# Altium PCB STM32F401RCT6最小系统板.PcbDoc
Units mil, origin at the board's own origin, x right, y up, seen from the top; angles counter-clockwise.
Board outline 2560 x 2610 mil, 2 copper layers (Top Layer, Bottom Layer); 73 components, 77 nets, 277 pads, 58 vias.
Unrouted connection lines stored in the file: 63.
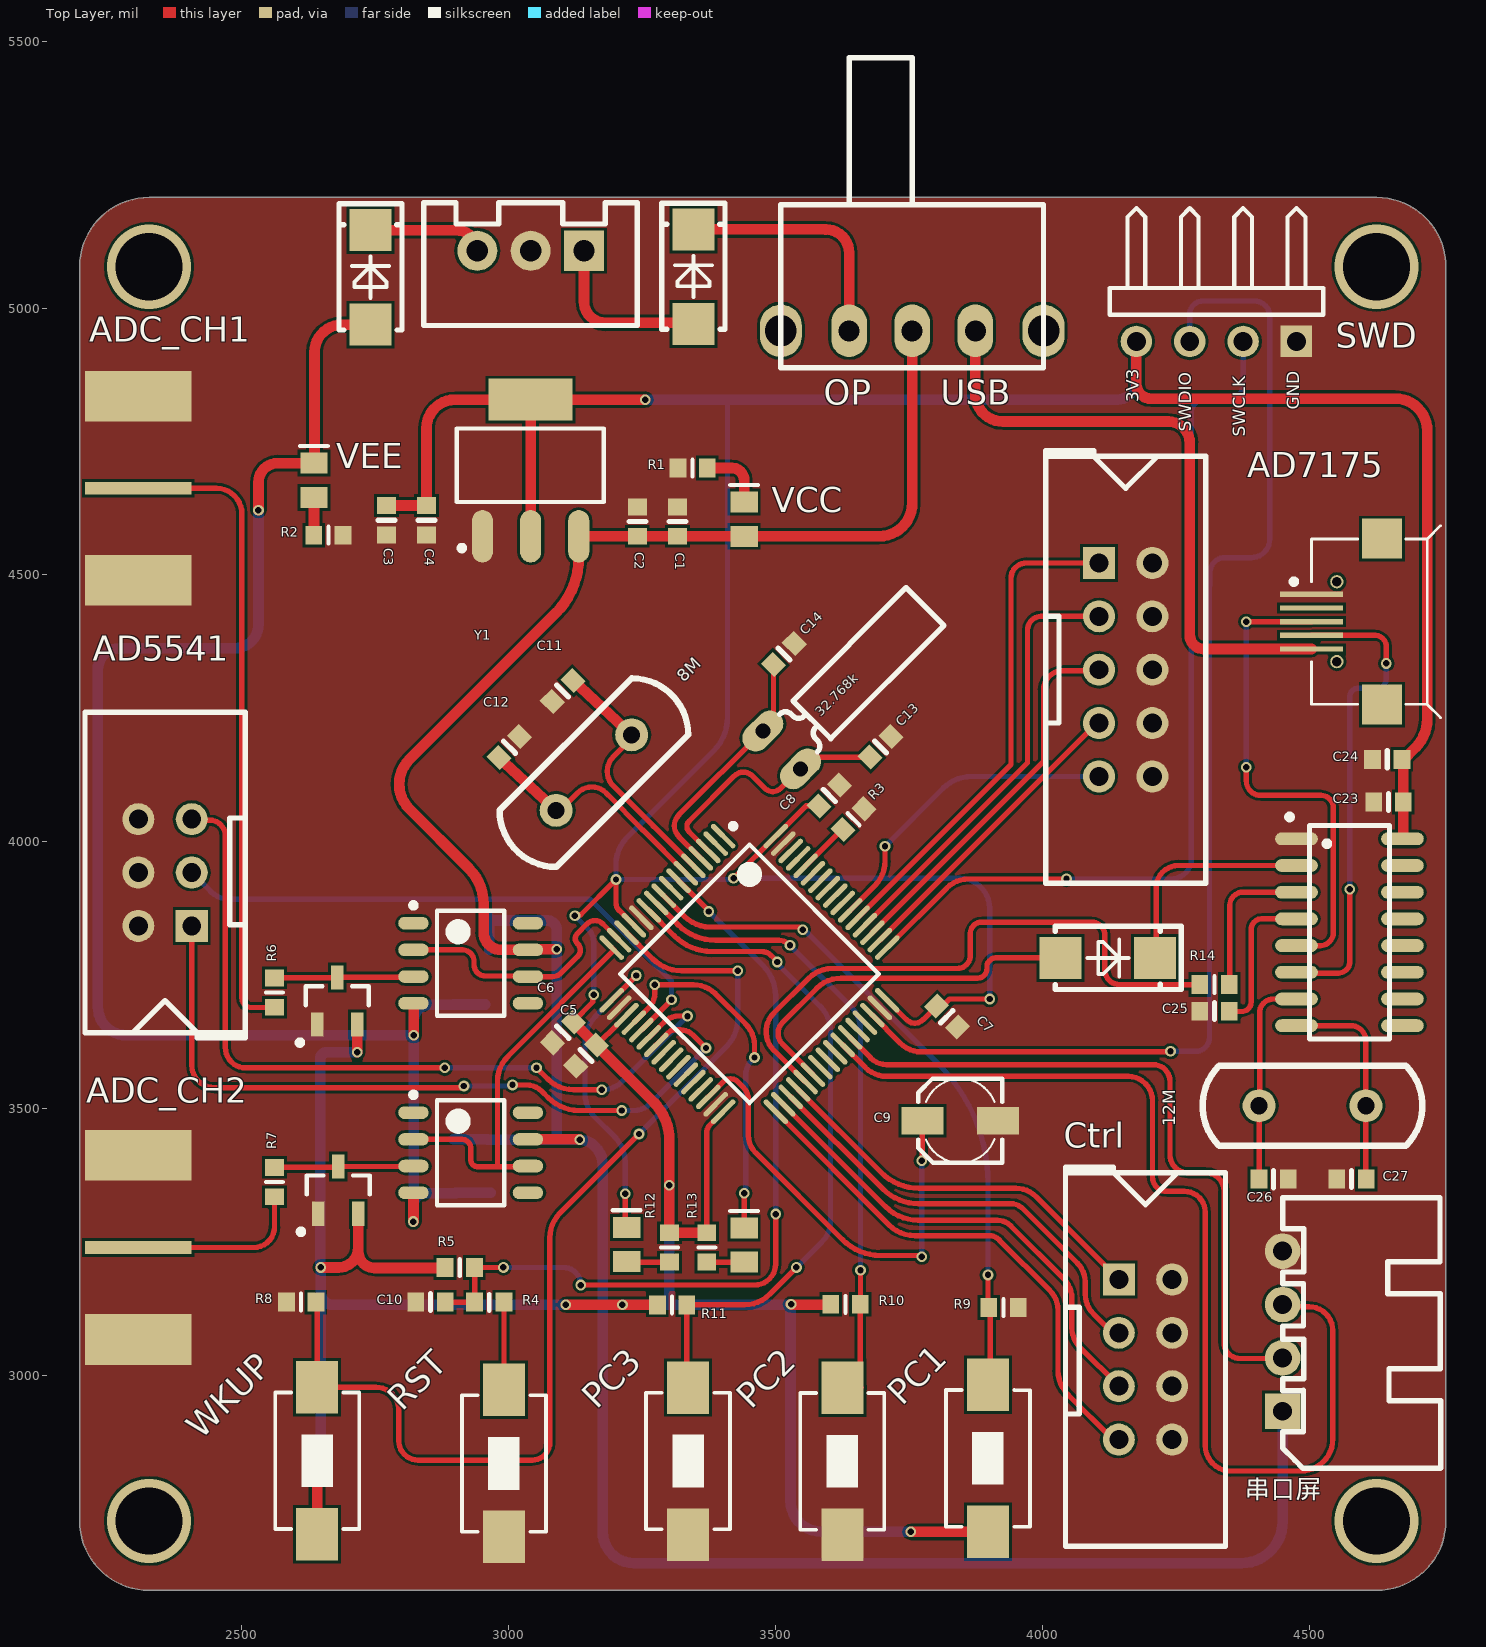
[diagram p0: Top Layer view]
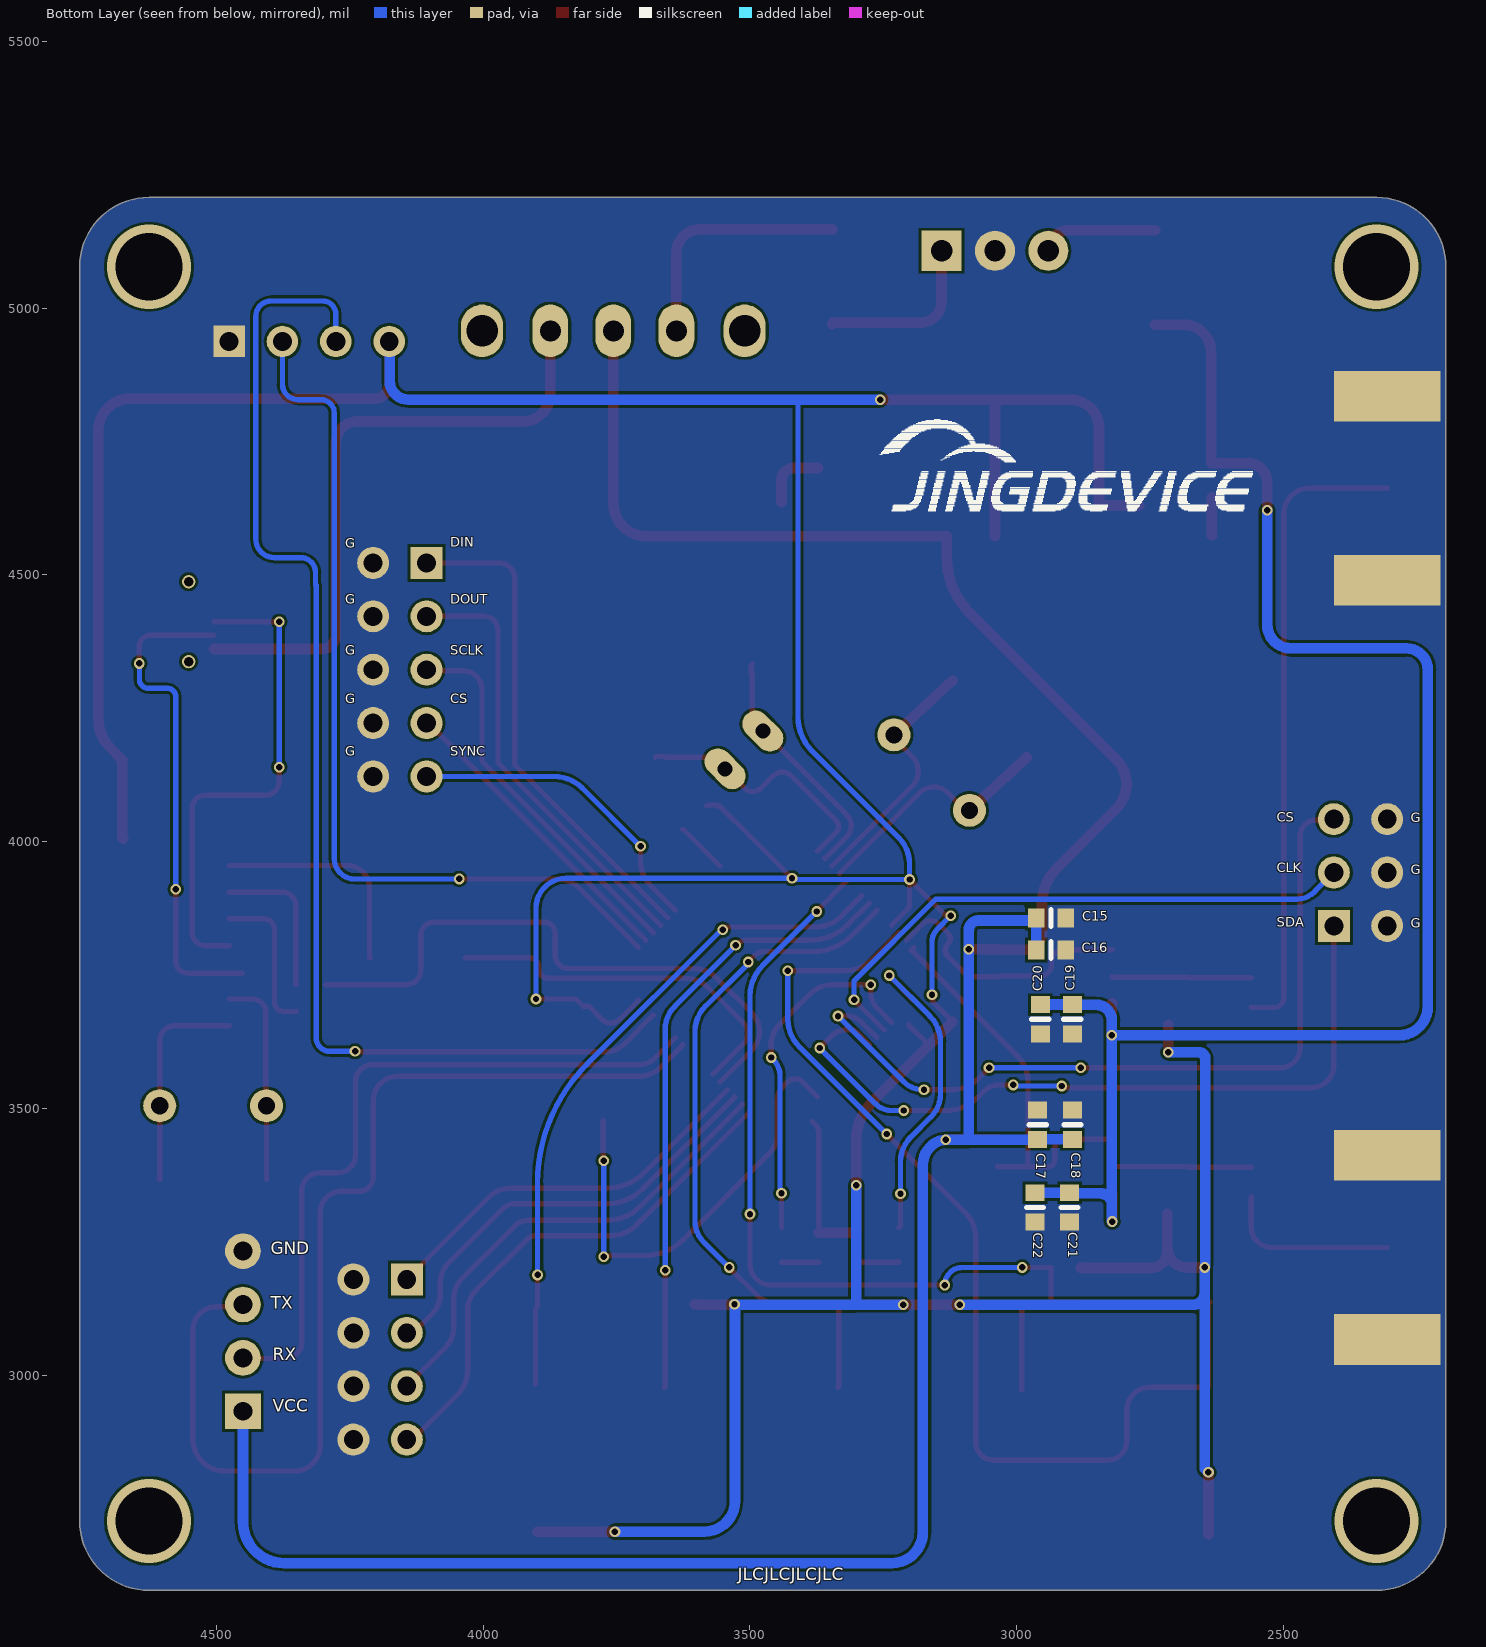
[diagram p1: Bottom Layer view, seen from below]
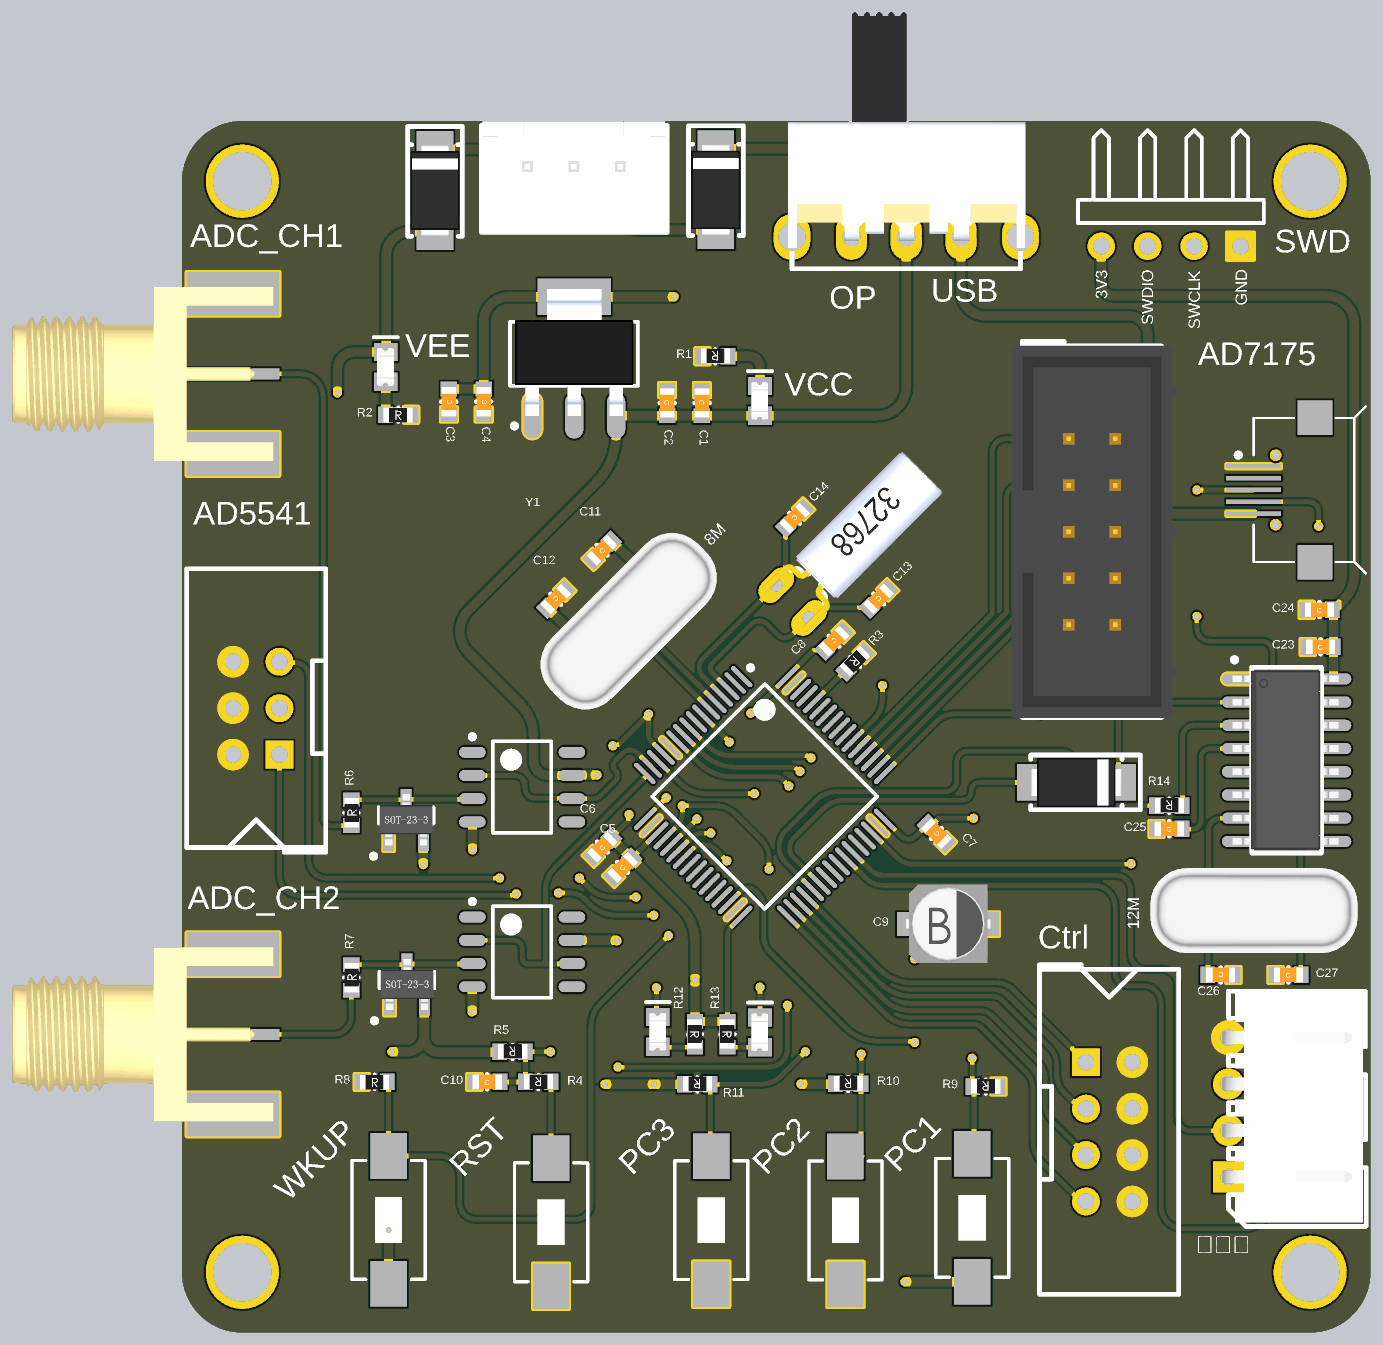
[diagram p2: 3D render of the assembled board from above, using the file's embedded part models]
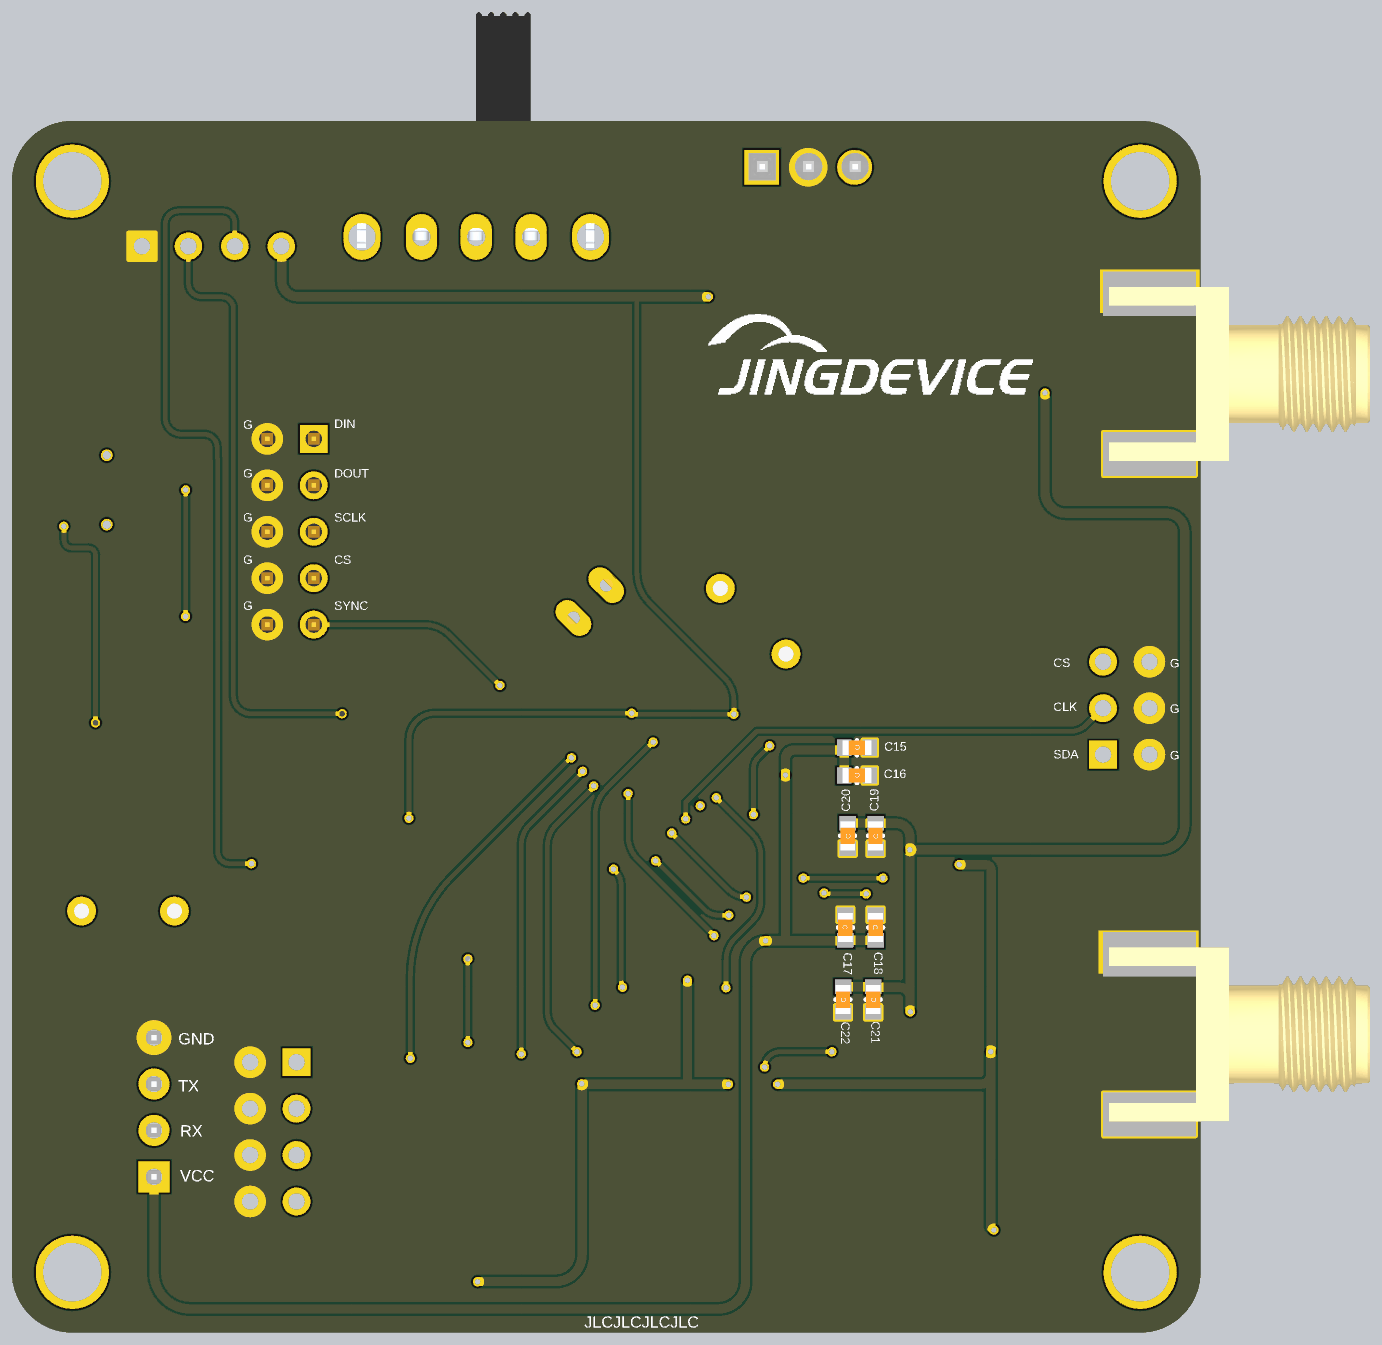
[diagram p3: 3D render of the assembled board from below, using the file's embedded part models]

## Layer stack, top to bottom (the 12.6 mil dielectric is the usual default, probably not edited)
Top Solder: solder mask 0.4, Solder Resist, Dk 3.5
Top Layer: signal copper 1.4
Dielectric 1: dielectric 12.6, FR-4, Dk 4.8
Bottom Layer: signal copper 1.4
Bottom Solder: solder mask 0.4, Solder Resist, Dk 3.5

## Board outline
2325.94,2597.49 cw(c2325.94,2727.49) 2195.94,2727.49 2195.94,5077.49 cw(c2325.94,5077.49) 2325.94,5207.49 4625.94,5207.49 cw(c4625.94,5077.49) 4755.94,5077.49 4755.94,2727.49 cw(c4625.94,2727.49) 4625.94,2597.49

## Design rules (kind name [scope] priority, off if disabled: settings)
Clearance [All] p1: gap=5 ignorepadtopadclearanceinfootprint=FALSE except(0: Arc-Hole Track-Hole SMDPad-Hole THPad-Hole Via-Hole Fill-Hole Poly-Hole Region-Hole Text-Hole)
PolygonConnect [All] p1: connectstyle=Direct reliefconductorwidth=10 reliefentries=4 polygonreliefangle="90 Angle" airgapwidth=10
RoutingVias [All] p1: holewidth=28 width=50 viastyle="Through Hole" minholewidth=28 minwidth=50 maxholewidth=28 maxwidth=50
SolderMaskExpansion [All] p1: expansion=4 istentingtop=FALSE
Width [All] p1: maxlimit=100 minlimit=10 preferedwidth=10
30 further rules are at their usual default settings.

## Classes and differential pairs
component class USB-TTL: C23 C24 C25 C26 C27 R14
component class STM32F401RCT6最小系统板: AD5541 AD7175 C1 C2 C3 C4 C5 C6 C7 C8 C9 C10 C11 C12 C13 C14 R1 R2 R3 R4 R5 RST SWD Y1 串口屏
component class Keys: R8 R9 R10 R11 R12 R13 WKUP
component class Analog: ADC_CH1 ADC_CH2 C15 C16 C17 C18 C19 C20 C21 C22 R6 R7

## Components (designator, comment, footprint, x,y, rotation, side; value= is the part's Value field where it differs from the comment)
AD5541 "DC-6P" DC-6P 2350.94,4027.49 r90 top
AD7175 "DC-10P" DC-10P 4105.94,4322.49 r90 top
ADC_CH1 "SMA" SMA1 2305.94,4662.49 r0 top
ADC_CH2 "SMA" SMA1 2305.94,3239.99 r0 top
C1 "Cap-S" C0603-L 3315.94,4600.05 r270 top value=100nF
C2 "Cap-S" C0603-L 3240.94,4600.05 r270 top value=10uF
C3 "Cap-S" C0603-L 2770.94,4602.49 r90 top value=100nF
C4 "Cap-S" C0603-L 2845.94,4602.49 r90 top value=10uF
C5 "Cap-S" C0603-L 3144.94,3599.49 r45 top value=100nF
C6 "Cap-S" C0603-L 3101.45,3643.01 r45 top value=10uF
C7 "Cap-S" C0603-L 3820.94,3672.49 r135 top value=100nF
C8 "Cap-S" C0603-L 3600.43,4086.98 r225 top value=10uF
C9 "C" C-RB-SD4 3845.94,3477.49 r0 top value=4.7uF
C10 "Cap-S" C0603-L 2853.38,3137.49 r0 top value=100nF
C11 "Cap-S" C0603-L 3100.94,4282.49 r45 top value=20pF
C12 "Cap-S" C0603-L 3000.94,4177.49 r225 top value=20pF
C13 "Cap-S" C0603-L 3696.45,4178.01 r225 top value=10pF
C14 "Cap-S" C0603-L 3515.43,4351.98 r225 top value=10pF
C15 "Cap-S" C0603-L 2935.94,3857.49 r0 bottom value=100nF
C16 "Cap-S" C0603-L 2935.94,3797.49 r0 bottom value=10uF
C17 "Cap-S" C0603-L 2960.94,3470.05 r270 bottom value=100nF
C18 "Cap-S" C0603-L 2895.94,3470.05 r270 bottom value=10uF
C19 "Cap-S" C0603-L 2895.94,3667.49 r90 bottom value=100nF
C20 "Cap-S" C0603-L 2955.94,3667.49 r90 bottom value=10uF
C21 "Cap-S" C0603-L 2900.94,3314.93 r90 bottom value=100nF
C22 "Cap-S" C0603-L 2965.94,3314.93 r90 bottom value=10uF
C23 "Cap-S" C0603-L 4648.38,4074.49 r0 top value=100nF
C24 "Cap-S" C0603-L 4645.94,4154.49 r0 top value=10uF
C25 "Cap-S" C0603-L 4322.38,3682.49 r0 top value=10nF
C26 "Cap-S" C0603-L 4433,3368 r180 top value=22pF
C27 "Cap-S" C0603-L 4579,3368 r0 top value=22pF
Ctrl "DC-8P" DC-8P 4201,3038 r270 top
D1 "D" D-SMA 2740.94,5057.49 r90 top
D2 "D" D-SMA 3345.94,5058.91 r90 top
D3 "D" D-SMA 4122.36,3782.49 r0 top
J1 "Power-3P" SIPA03 3140.94,5107.49 r180 top
LED3 "LED" Led-0805_L 3220.94,3245.49 r90 top
LED4 "LED" Led-0805_L 3440.94,3244.49 r90 top
PC1 "SW-PB2" SW-PB2-SMD 3898,2847 r180 top (schematic designator S1)
PC2 "SW-PB2" SW-PB2-SMD 3625,2837 r0 top (schematic designator S2)
PC3 "SW-PB2" SW-PB2-SMD 3335.94,2837.49 r0 top (schematic designator S3)
R1 "R" R0603-L 3344.38,4700.49 r180 top value=1K
R2 "R" R0603-L 2661.94,4574.49 r0 top value=1K
R3 "R" R0603-L 3645.94,4042.49 r225 top value=10K
R4 "R" R0603-L 2963.5,3137.49 r180 top value=100R
R5 "R" R0603-L 2907.94,3202.49 r180 top value=10K
R6 "R" R0603-L 2560.94,3717.49 r90 top value=100R
R7 "R" R0603-L 2560.94,3362.49 r90 top value=100R
R8 "R" R0603-L 2610.94,3137.49 r0 top value=1K
R9 "R" R0603-L 3926.94,3127.49 r180 top value=1K
R10 "R" R0603-L 3630.94,3133.49 r180 top value=1K
R11 "R" R0603-L 3305.94,3132.49 r180 top value=1K
R12 "R" R0603-L 3300.94,3240.05 r270 top value=1K
R13 "R" R0603-L 3370.94,3240.05 r270 top value=1K
R14 "R" R0603-L 4322.38,3732.49 r180 top value=100
RST "SW-PB2" SW-PB2-SMD 2990.94,2837.49 r180 top
SWD "Header 4H" HDR1X4H 4475.94,4937.49 r180 top
U1 "STM32F401RCT6" STM-LQFP64_L 3450.94,3752.49 r315 top
U3 "OPA192" SOIC127P600X175-8N 2928.66,3772.49 r0 top
U4 "OPA192" SOIC127P600X175-8N 2928.66,3417.49 r0 top
U5 "BAT54S" SOT-23-3 2678.95,3702 r90 top
U6 "BAT54S" SOT-23-3 2680.94,3347.49 r90 top
U7 "CH340G" SOP-16 4575.94,3839.49 r0 top
U10 "AMS1117" SOT-223 3040.94,4697.49 r0 top
USB "USB_Mini/Micro" USB_Micro 4720.94,4412.49 r0 top
USB "SW-SPDT" SW-SPDT 3755.94,4957.49 r90 top (schematic designator POWER)
VCC "LED" Led-0805_L 3440.94,4604.49 r90 top (schematic designator LED1)
VEE "LED" Led-0805_L 2634.94,4677.49 r90 top (schematic designator LED2)
WKUP "SW-PB2" SW-PB2-SMD 2640.94,2842.49 r180 top
Y1 "XTAL" XTAL-PB2-DIP 3160.94,4142.49 r45 top value=8M
Y2 "XTAL" XTAL-32768 3475.94,4207.49 r315 top value=32.768K
Y3 "XTAL" XTAL-PB2-DIP 4515.94,3513.49 r0 top value=12M
串口屏 "Header 4" XH2.54-WI-4P 4450,3083 r90 top

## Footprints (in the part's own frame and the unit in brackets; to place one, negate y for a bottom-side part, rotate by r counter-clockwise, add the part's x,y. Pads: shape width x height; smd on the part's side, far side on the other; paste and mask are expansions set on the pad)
C0603-L [mm] "贴片电容0603 高密度"
  rect 0.8x0.9 smd: 1(-0.7,0) 2(0.7,0)
  silkscreen extent 0,-0.39 0,0.41, body extent -0.8,-0.4 0.8,0.41, height 0.88
C-RB-SD4 [mm] "贴片铝电解"
  rect 2x1.3 smd: 1(-1.8,0) 2(1.8,0)
  silkscreen extent -2,-2 2,2, body extent -2.29,-2.14 2.31,2.16, height 5.2
D-SMA [mm]
  rect 2x2 smd: 1(-2.25,0) 2(2.25,0)
  silkscreen extent -2.5,-1.5 3.5,1.5, body extent -2.5,-1.35 2.5,1.35, height 2.15
DC-6P [mil]
  rect 60x60 hole 35.43: 1(-185,-55)
  round 60 hole 35.43: 2(-85,-55) 3(15,-55) 4(15,45) 5(-85,45) 6(-185,45)
  silkscreen extent -395,-155 215,145, body extent -386,-156 216,145, height 236
DC-8P [mil]
  rect 60x60 hole 35.43: 1(-142,-58)
  round 60 hole 35.43: 2(-42,-58) 3(58,-58) 4(158,-58) 5(158,42) 6(58,42) 7(-42,42) 8(-142,42)
  silkscreen extent -352,-158 358,142, body extent -342,-159 358,142, height 236
DC-10P [mil]
  rect 60x60 hole 35.43: 1(200,0)
  round 60 hole 35.43: 2(100,0) 3(0,0) 4(-100,0) 5(-200,0) 6(-200,-100) 7(-100,-100) 8(0,-100) 9(100,-100) 10(200,-100)
  silkscreen extent -400,-200 410,100, body extent -401,-233 401,123, height 357
HDR1X4H [mm] "Connector; Header; 4 Position; Right Angle"
  rect 1.5x1.5 hole 0.9: 1(0,0)
  round 1.5 hole 0.9: 2(2.54,0) 3(5.08,0) 4(7.62,0)
  silkscreen extent -1.27,-6.35 8.89,-1.27
Led-0805_L [mm] "贴片LED0805-高密度"
  rect 1x1.3 smd: 1(-0.813,0) 2(0.813,0)
  silkscreen extent 1.63,-0.66 1.63,0.66, body extent -1.03,-0.44 1.03,0.47, height 0.85
R0603-L [mm] "贴片电阻0603 高密度"
  rect 0.8x0.9 smd: 1(-0.7,0) 2(0.7,0)
  silkscreen extent 0,-0.39 0,0.41, body extent -0.81,-0.43 0.79,0.39, height 0.53
SIPA03 [mil]
  rect 75x75 hole 40: 1(0,0)
  round 75 hole 40: 2(100,0) 3(200,0)
  silkscreen extent -100,-90 300,140, body extent -96,-99 298,137, height 276
SMA1 [mil]
  rect 200x24 smd: 1(0,0)
  rect 200x95 smd: 2(0,-172.5) 2(0,172.5)
  rect 200x95 smd far side: 2(0,-172.5)
  rect 200x95 smd far side mask+4: 2(0,172.5)
  body extent -475,-187 87,187, height 171
SOIC127P600X175-8N [mm] "SOIC, 8-Leads, Body 4.91x3.90mm, Pitch 1.27mm, IPC Medium Density"
  oval 1.45x0.6 smd: 1(-2.725,1.905) 2(-2.725,0.635) 3(-2.725,-0.635) 4(-2.725,-1.905) 5(2.725,-1.905) 6(2.725,-0.635) 7(2.725,0.635) 8(2.725,1.905)
  silkscreen extent -2.85,-2.5 1.6,2.88, body extent -2,-2.5 2,2.5, height 1.75
SOP-16 [mil]
  oval 80x24 smd: 1(-100,166.09) 2(-100,116.09) 3(-100,66.09) 4(-100,16.09) 5(-100,-33.91) 6(-100,-83.91) 7(-100,-133.91) 8(-100,-183.91) 9(98.5,-183.91) 10(98.5,-133.91) 11(98.5,-83.91) 12(98.5,-33.91) 13(98.5,16.09) 14(98.5,66.09) 15(98.5,116.09) 16(98.5,166.09)
  silkscreen extent -118,-209 74,212, body extent -117,-202 111,184, height 69
SOT-23-3 [mm]
  rect 1.15x0.6 smd: 1(-1.13,0.96) 2(1.12,0.01) 3(-1.13,-0.94)
  silkscreen extent -2.11,-1.49 0.69,1.91, body extent -1.4,-1.45 1.4,1.45, height 1.2
SOT-223 [mm]
  oval 1x2.5 smd: 1(-2.29,-3.175) 2(0,-3.175) 3(2.29,-3.175)
  rect 4x2 smd: 2(0,3.325)
  silkscreen extent -3.52,-3.86 3.48,1.96, body extent -3.25,-3.2 3.25,3.76, height 1.66
STM-LQFP64_L [mm] "Thin QFP, 64-Leads, Body 10x10mm, Pitch 0.5mm, IPC High Density"
  oval 1.55x0.25 smd: 1(-5.525,3.75) 2(-5.525,3.25) 3(-5.525,2.75) 4(-5.525,2.25) 5(-5.525,1.75) 6(-5.525,1.25) 7(-5.525,0.75) 8(-5.525,0.25) 9(-5.525,-0.25) 10(-5.525,-0.75) 11(-5.525,-1.25) 12(-5.525,-1.75) 13(-5.525,-2.25) 14(-5.525,-2.75) 15(-5.525,-3.25) 16(-5.525,-3.75) 33(5.525,-3.75) 34(5.525,-3.25) 35(5.525,-2.75) 36(5.525,-2.25) 37(5.525,-1.75) 38(5.525,-1.25) 39(5.525,-0.75) 40(5.525,-0.25) 41(5.525,0.25) 42(5.525,0.75) 43(5.525,1.25) 44(5.525,1.75) 45(5.525,2.25) 46(5.525,2.75) 47(5.525,3.25) 48(5.525,3.75)
  oval 0.25x1.55 smd: 17(-3.75,-5.525) 18(-3.25,-5.525) 19(-2.75,-5.525) 20(-2.25,-5.525) 21(-1.75,-5.525) 22(-1.25,-5.525) 23(-0.75,-5.525) 24(-0.25,-5.525) 25(0.25,-5.525) 26(0.75,-5.525) 27(1.25,-5.525) 28(1.75,-5.525) 29(2.25,-5.525) 30(2.75,-5.525) 31(3.25,-5.525) 32(3.75,-5.525) 49(3.75,5.525) 50(3.25,5.525) 51(2.75,5.525) 52(2.25,5.525) 53(1.75,5.525) 54(1.25,5.525) 55(0.75,5.525) 56(0.25,5.525) 57(-0.25,5.525) 58(-0.75,5.525) 59(-1.25,5.525) 60(-1.75,5.525) 61(-2.25,5.525) 62(-2.75,5.525) 63(-3.25,5.525) 64(-3.75,5.525)
  silkscreen extent -5.65,-4.35 4.35,4.55, body extent -5,-5 5,5, height 1.6
SW-PB2-SMD [mm] "贴片2脚微动开关"
  rect 2x2.5 smd: 1(0,3.556) 2(0,-3.444)
  silkscreen extent -2,-3.19 2,3.31, body extent -1.93,-3.94 1.92,3.95, height 2.5
SW-SPDT [mm] "侧卧拨动开关"
  oval 2.5x1.7 hole 1: 1(0,3) 2(0,0) 3(0,-3)
  oval 2.5x2 hole 1.5: 4(0,-6.25) 4(0,6.25)
  silkscreen extent -1.75,-6.25 13,6.25, body extent -0.61,-6.52 12.29,6.48, height 5.75
USB_Micro [mm] "5P 贴片 带定位柱"
  rect 3x0.25 smd: 1(-5.508,-1.3) 2(-5.508,-0.65) 3(-5.508,0) 4(-5.508,0.65) 5(-5.508,1.3)
  rect 1.9x1.9 smd: 6(-2.15,-3.95) 6(-2.15,3.95)
  round 0.635 hole 0.457 unplated: MH1(-4.3,1.9) MH2(-4.3,-1.9)
  silkscreen extent -6.47,-4.57 0.63,4.57
XH2.54-WI-4P [mm] "接插件，4P"
  rect 1.7x1.7 hole 0.9: 1(-3.81,0)
  round 1.7 hole 0.9: 2(-1.27,0) 3(1.27,0) 4(3.81,0)
  silkscreen extent -6.53,-7.53 6.35,0, body extent -6.31,-7.35 6.31,0.35, height 5.73
XTAL-32768 [mil]
  oval 50x88 hole 28: 1(0,0) 2(100,0)
  silkscreen extent 0,45 100,380, body extent -18,-28 118,396, height 126
XTAL-PB2-DIP [mil]
  round 62 hole 32: 1(-110,-8) 2(90,-8)
  silkscreen extent -216,-83 196,67, body extent -234,-99 212,85, height 142

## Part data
C1 C2 C3 C4 C5 C6 C7 C8 C10 C11 C12 C13 C14 C15 C16 C17 C18 C19 C20 C21 C22 C23 C24 C25 C26 C27: "贴片瓷片电容"
C9: library part Cap-Pol-ES, "极性贴片电解电容"
D1 D2 D3: library part Diode, "二极管"
J1: "供电端子"
LED3 LED4 VCC VEE: "发光二极管"
PC1 PC2 PC3 RST WKUP: "贴片式2脚微动开关"
R1 R2 R3 R4 R5 R6 R7 R8 R9 R10 R11 R12 R13 R14: library part Res, "贴片电阻"
SWD: "Header, 4-Pin, Right Angle"
U1: "ARM Cortex-M4 32-bit MCU+FPU, 105 DMIPS, 256 kB Flash, 64 kB Internal RAM, 48 I/Os, 64-pin LQFP, -40 to 85 degC, Tray", I/Os (High Current)=48, Manufacturer=STMicroelectronics, Operating Frequency(F) (Processor speed) (MHz)=84, Supplier Part Number 1=497-14047-ND, Supply Voltage(Vcc) max (V)=3.6, Supply Voltage(Vcc) min (V)=1.8
U7: "SOP16"
USB: library part USB, "Mini/Micro USB母口"
USB: "SPDT Subminiature Toggle Switch, Right Angle Mounting, Vertical Actuation"
Y1 Y2 Y3: "晶振"
串口屏: "Header, 4-Pin"

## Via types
v1: diameter 20, hole 12, Top Layer to Bottom Layer, 54 vias
v2: diameter 157.48, hole 125.98, Top Layer to Bottom Layer, 4 vias

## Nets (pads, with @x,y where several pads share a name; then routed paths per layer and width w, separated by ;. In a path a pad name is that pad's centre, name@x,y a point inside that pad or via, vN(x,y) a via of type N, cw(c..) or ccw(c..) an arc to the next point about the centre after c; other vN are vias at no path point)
3V3: C3.2 C4.2 C5.2 C6.2 C7.2 C8.2 C23.2 C24.2 PC1.1 R5.2 R10.2 R11.2 R12.1 R13.1 SWD.4 U1.13 U1.19 U1.32 U1.48 U1.64 U5.3 U6.3 U7.16 U10.2 WKUP.1 | length 10339.7
  Top Layer w10: C6.2 3120.94,3663.49 3157.26,3699.82 3157.26,3711.82 v1(3158.94,3713.49) ; v1(3123.94,3861.49) 3125.85,3863.41 3134.85,3863.41 v1(3200.94,3929.49) 3200.94,3903.36 3200.94,3884.72 ccw(c3219.05,3884.72) 3206.25,3871.91 U1.13 ; C5.2@3164.45,3618.98 3167.43,3618.98 3167.43,3621.98 U1.19@3202.59,3657.15 ; R13.1 3370.94,3454.94 cw(c3392.09,3454.94) 3377.13,3469.89 U1.32@3383.33,3476.09 ; v1(3421.19,3931.74) 3421.4,3931.74 U1.64 3557.15,4067.49 3562.96,4067.49 3564.35,4068.89 3579.55,4068.89 C8.2 ; U1.48 3745.73,3666.49 ccw(c3760.84,3681.6) 3775.94,3666.49 3801.43,3691.98 3812.41,3691.98 3825.92,3705.49 v1(3900.94,3705.49)
  Top Layer w20: WKUP.1 v1(2640.94,2818.49) ; v1(2647.94,3202.49) 2680.94,3202.49 ccw(c2680.94,3239.49) 2717.93,3239.49 ; v1(2715.94,3605.49) U5.3 ; U6.3 2717.93,3239.49 ; C3.2 C4.2 2845.94,4775.49 cw(c2898.85,4775.49) 2898.85,4828.4 U10.2@3040.94,4828.4 ; R5.2 cw(c2879.38,3202.49) 2879.38,3201.49 2748.94,3201.49 cw(c2748.94,3232.5) 2717.93,3232.5 2717.93,3239.49 ; U10.2@3040.94,4572.49 U10.2@3040.94,4828.4 ; v1(3106.94,3132.49) v1(3212.94,3132.49) R11.2 ; C6.2 3164.45,3618.98 3271.65,3511.76 cw(c3200.94,3441.05) 3300.94,3441.05 v1(3300.94,3356.49) R12.1 R13.1 ; v1(3255.94,4828.49) 3255.94,4828.4 U10.2@3040.94,4828.4 ; v1(3528.94,3133.49) 3529.94,3132.49 3597.63,3132.49 3598.63,3133.49 R10.2 ; v1(3753,2707) PC1.1 ; SWD.4 4175.94,4857.49 ccw(c4202.94,4857.49) 4202.94,4830.49 4660.94,4830.49 cw(c4660.94,4770.49) 4720.94,4770.49 4720.94,4230.31 cw(c4644.12,4230.31) 4698.45,4176.01 4675.94,4153.49 4675.94,4007.08 U7.16
  Bottom Layer w10: v1(3123.94,3861.49) 3148.57,3836.87 cw(c3123.53,3811.83) 3158.94,3811.83 v1(3158.94,3713.49) ; 3409.94,4828.49 3409.94,4233.86 cw(c3319.72,4233.86) 3383.52,4170.07 3221.45,4008 ccw(c3270.95,3958.49) 3200.94,3958.51 v1(3200.94,3929.49) 3418.94,3929.49 v1(3421.19,3931.74) 3844.69,3931.74 cw(c3844.69,3875.49) 3900.94,3875.49 v1(3900.94,3705.49)
  Bottom Layer w20: v1(2640.94,2818.49) 2647.94,2825.49 2647.94,3154.49 ; v1(2715.94,3605.49) 2658.66,3605.49 ccw(c2658.66,3593.78) 2646.94,3593.78 2646.94,3543.49 2646.94,3208.74 ccw(c2666.94,3208.74) v1(2647.94,3202.49) 2647.94,3154.49 ; v1(3106.94,3132.49) 2669.94,3132.49 cw(c2669.94,3154.49) 2647.94,3154.49 ; v1(3212.94,3132.49) 3300.94,3132.49 ; v1(3255.94,4828.49) 3409.94,4828.49 4139.94,4828.49 ccw(c4139.94,4863.49) 4174.94,4863.49 4174.94,4936.49 SWD.4 ; v1(3300.94,3356.49) 3300.94,3132.49 ; v1(3528.94,3133.49) ccw(c3528.94,3132.49) v1@3527.94,3132.49 ; v1@3753,2707.49 3585.68,2707.49 cw(c3585.6,2765.15) 3527.94,2765.26 v1@3527.94,3132.49 ; 3300.94,3132.49 v1@3527.94,3132.49
ADC_CH1: U1.15 U3.2 U3.6 | length 503
  Top Layer w10: U3.2 2912.94,3797.49 cw(c2912.94,3775.49) 2934.94,3775.49 2934.94,3769.49 ccw(c2955.94,3769.49) 2955.94,3748.49 3034.94,3748.49 cw(c3034.94,3747.49) U3.6 3081,3747.49 ccw(c3081,3772.81) 3098.9,3754.91 3129.08,3785.09 ccw(c3117.18,3796.99) 3129.08,3808.89 3128.38,3809.6 cw(c3137.54,3818.76) 3128.38,3827.93 3146.94,3846.49 cw(c3161.46,3831.97) 3175.99,3846.49 U1.15
ADC_CH2: U1.16 U4.2 U4.6 | length 753.8
  Top Layer w10: U4.2 2911.94,3442.49 cw(c2911.94,3425.49) 2928.94,3425.49 2928.94,3403.49 ccw(c2940.94,3403.49) 2940.94,3391.49 2978.94,3391.49 ; 2978.94,3551.51 2978.94,3391.49 ; 2978.94,3551.54 cw(c3044.1,3551.51) 2998.02,3597.58 3197.49,3797.04 3197.49,3797.15 U1.16 ; U4.6 cw(c3034.94,3392.49) 3034.94,3391.49 2978.94,3391.49
BOOT0: R3.2 U1.60 | length 98.6
  Top Layer w10: U1.60 3624.02,4023.01 R3.2
D+: U7.5 USB.3@4504.09,4412.49 | length 928.2
  Top Layer w10: v1(4381.94,4412.49) USB.3@4504.09,4412.49 ; v1(4382,4140) 4382,4114 ccw(c4409,4114) 4409,4087 4522,4087 cw(c4522,4064) 4545,4064 4545,3830 cw(c4520.59,3830) 4520.59,3805.59 U7.5
  Bottom Layer w10: v1@4381.94,4141 v1(4381.94,4412.49)
D-: U7.6 USB.2@4504.09,4386.9 | length 934.1
  Top Layer w10: U7.6@4450.99,3754 4554,3754 ccw(c4554,3776) 4576,3776 v1(4576,3911) ; USB.2@4504.09,4386.9 4623.25,4386.9 cw(c4623.25,4365.95) 4644.2,4365.95 v1(4644.2,4334.23)
  Bottom Layer w10: v1(4576,3911) 4576,4272.43 4575.94,4272.49 cw(c4590.94,4272.49) 4590.94,4287.49 4626.94,4287.49 ccw(c4626.94,4304.49) 4643.94,4304.49 4643.94,4334.23 v1(4644.2,4334.23)
GND: AD5541.4 AD5541.5 AD5541.6 AD7175.6 AD7175.7 AD7175.8 AD7175.9 AD7175.10 ADC_CH1.2 ADC_CH2.2 C1.1 C2.1 C3.1 C4.1 C5.1 C6.1 C7.1 C8.1 C9.2 C10.1 C11.1 C12.1 C13.1 C14.1 C15.1 C16.1 C17.1 C18.1 C19.1 C20.1 C21.1 C22.1 C23.1 C24.1 C25.1 C26.1 C27.1 Ctrl.5 Ctrl.6 Ctrl.7 Ctrl.8 J1.2 PC2.2 PC3.2 R1.2 R2.2 R3.1 R8.1 R9.1 RST.1 SWD.1 U1.12 U1.18 U1.31 U1.47 U1.63 U5.1 U6.1 U7.1 U10.1 USB.5 串口屏.4
GPIO_LED1: LED3.2 U1.17 | length 601.3
  Top Layer w10: U1.17 3238.94,3749.29 v1(3238.94,3749.49) ; v1(3217.94,3340.31) 3217.94,3280.49 LED3.2
  Bottom Layer w10: v1(3217.94,3340.31) 3217.94,3400.18 ccw(c3152.01,3400.18) 3198.63,3446.8 3160.6,3484.84 cw(c3203.22,3527.46) 3142.94,3527.43 3142.94,3625.41 cw(c3210.74,3625.41) 3162.8,3673.35 v1(3238.94,3749.49)
GPIO_LED2: LED4.2 U1.20 | length 676.4
  Top Layer w10: U1.20 3262.45,3689.28 ccw(c3235.37,3716.36) 3273.67,3716.3 ccw(c3235.37,3716.36) 3273.67,3716.36 v1(3273.67,3732.22) 3346.16,3732.22 cw(c3346.16,3674.15) 3387.22,3715.21 3443.98,3658.45 cw(c3404.53,3618.99) 3460.33,3619.06 cw(c3404.53,3618.99) 3460.33,3618.99 v1(3460.33,3595.88) ; LED4.2 v1(3440.94,3341.49)
  Bottom Layer w10: v1(3440.94,3341.49) 3442.85,3343.41 3442.85,3350.48 3443.74,3351.37 3443.74,3562.11 ; 3443.75,3562.15 cw(c3485.24,3562.11) 3455.9,3591.45 v1(3460.33,3595.88)
KEY_S1: PC1.2 R9.2 U1.9 | length 1266.2
  Top Layer w10: U1.9 3329.1,3860.42 ccw(c3377.2,3908.51) 3377.2,3840.49 3379.4,3840.49 3527.89,3840.49 3538.87,3840.49 cw(c3538.87,3823.42) v1(3550.94,3835.49) ; R9.2@3897.94,3128.93 v1(3897.94,3188.49) ; PC1.2@3901.94,2983.09 R9.2@3901.94,3124.93
  Bottom Layer w10: v1(3550.94,3835.49) 3550.94,3837.49 3805.92,3582.51 3805.99,3582.45 cw(c3583.65,3360.31) 3897.94,3360.31 v1(3897.94,3188.49)
KEY_S2: PC2.1 R10.1 U1.10 | length 1159.3
  Top Layer w10: U1.10 3316.89,3844.78 ccw(c3387.6,3915.49) 3387.6,3815.49 3402.03,3815.49 3505.97,3815.49 cw(c3505.97,3786.59) 3519.39,3812.19 cw(c3505.97,3786.59) 3526.41,3807.03 v1(3526.94,3806.49) ; R10.1@3658.5,3131.49 3658.5,2979.94 ccw(c3660.94,2979.93) PC2.1@3660.94,2977.49 ; R10.1 3659.94,3134.93 3658.94,3135.93 v1(3658.94,3197.49)
  Bottom Layer w10: v1(3526.94,3806.49) 3526.94,3805.49 3641.18,3691.25 cw(c3598.31,3648.38) 3658.94,3648.38 v1(3658.94,3197.49)
KEY_S3: PC3.1 R11.1 U1.11 | length 1298.8
  Top Layer w10: U1.11 3310.05,3823.78 ccw(c3380.77,3894.49) 3380.77,3794.49 3474.05,3794.49 cw(c3474.05,3770.6) 3490.94,3787.5 3503.05,3775.39 v1(3503.05,3774.89) ; PC3.1 cw(c3335.94,2979.93) 3333.5,2979.93 R11.1 3441.62,3132.49 ; 3441.67,3132.49 ccw(c3441.62,3198.44) 3488.26,3151.81 v1(3538.94,3202.49)
  Bottom Layer w10: v1(3503.05,3774.89) 3503.05,3772.39 3583.48,3691.95 cw(c3536.51,3644.98) 3602.94,3644.98 3602.94,3289.03 ; v1(3538.94,3202.49) 3587.01,3250.56 ccw(c3548.54,3289.03) 3602.94,3288.99
NetADC_CH1_1: ADC_CH1.1 R6.1 | length 1199.9
  Top Layer w10: ADC_CH1.1 2451.94,4662.49 cw(c2451.94,4614.49) 2499.94,4614.49 2499.94,3707.49 ccw(c2517.94,3707.49) 2517.94,3689.49 2560.5,3689.49 R6.1
NetADC_CH2_1: ADC_CH2.1 R7.1 | length 333.4
  Top Layer w10: ADC_CH2.1 2522.39,3239.99 ccw(c2522.45,3278.49) 2560.94,3278.43 2560.94,3278.51 R7.1
NetC9_1: C9.1 U1.30 | length 853.8
  Top Layer w10: U1.30 3401.65,3550.09 cw(c3415.5,3536.25) 3429.34,3550.09 3439.14,3540.29 cw(c3415.49,3516.64) 3448.94,3516.64 3448.94,3449.96 ccw(c3494.56,3449.96) 3462.3,3417.7 3625.71,3254.29 ccw(c3696.42,3325) 3696.42,3225 v1@3775,3225 ; v1@3775,3405 3774.94,3405.06 3774.94,3477.49 C9.1
  Bottom Layer w10: v1(3773.94,3222.49) v1(3773.94,3402.49)
NetC25_2: C25.2 U7.4 | length 283.9
  Top Layer w10: C25.2 4349.94,3682 4373,3682 ccw(c4373,3700) 4391,3700 4391,3836 cw(c4410.59,3836) 4410.59,3855.59 U7.4
NetC26_2: C26.2 U7.7 Y3.1 | length 396.5
  Top Layer w10: C26.2 4405.94,3368 Y3.1 4407,3506.55 4407,3680 cw(c4432.59,3680) 4432.59,3705.59 U7.7
NetC27_2: C27.2 U7.8 Y3.2 | length 407.5
  Top Layer w10: U7.8 4577.41,3655.59 cw(c4577.41,3627) 4606,3627 4606,3505.49 Y3.2 4605.94,3368 C27.2 ; Y3.2@4590,3506.43 ccw(c4590.94,3506.43) Y3.2@4590.94,3505.49
NetD1_2: D1.2 J1.3 | length 222
  Top Layer w20: D1.2 2902.36,5146.08 cw(c2902.36,5107.49) J1.3
NetD2_1: D2.1 J1.1 | length 324.1
  Top Layer w20: J1.1 3140.94,5012.49 ccw(c3180.94,5012.49) 3180.94,4972.49 3343.78,4972.49 cw(c3343.78,4970.33) D2.1
NetD3_2: D3.2 U7.2 | length 419.4
  Top Layer w10: D3.2 ccw(c4210.94,3784.55) 4213,3784.55 4213,3914 cw(c4254.59,3914) 4254.59,3955.59 U7.2
NetLED1_2: R1.1 VCC.2 | length 123.1
  Top Layer w20: R1.1 3417.94,4700.49 cw(c3417.94,4677.49) 3440.94,4677.49 VCC.2
NetLED2_1: R2.1 VEE.1 | length 71.6
  Top Layer w20: R2.1 2634.94,4574.49 VEE.1
NetLED3_1: LED3.1 R12.2 | length 80.6
  Top Layer w10: LED3.1 ccw(c3221.94,3213.49) 3221.94,3212.49 R12.2
NetLED4_1: LED4.1 R13.2 | length 70
  Top Layer w10: R13.2 LED4.1
NetR4_1: R4.1 RST.2 | length 164.5
  Top Layer w10: RST.2 2990.94,3137.49 R4.1
NetR6_2: R6.2 U3.3 U5.2 | length 261.8
  Top Layer w10: R6.2 2677.52,3745.05 ccw(c2677.52,3746.08) U5.2 2819.96,3746.08 ccw(c2819.96,3747.49) U3.3
NetR7_2: R7.2 U4.3 U6.2 | length 261.8
  Top Layer w10: R7.2 2679.01,3390.05 ccw(c2679.01,3391.57) U6.2 2820.45,3391.57 ccw(c2820.45,3392.49) U4.3
NetR14_1: R14.1 U7.3 | length 288.1
  Top Layer w10: R14.1 ccw(c4349.94,3733.55) 4351,3733.55 4351,3881 cw(c4375.59,3881) 4375.59,3905.59 U7.3
NRST: C10.2 R4.2 R5.1 U1.7 | length 1513.8
  Top Layer w10: C10.2 R4.2 R5.1@2935.94,3202.49 ; R5.1 R5.1@2935.94,3202.49 ; v1(2989.94,3202.49) R5.1@2935.94,3202.49 ; v1(3134.94,3169.49) 3460.51,3169.49 ccw(c3460.55,3208.88) 3499.94,3208.85 3499.94,3208.95 v1(3499.94,3302.49) ; U1.7 v1@3373.94,3871.25
  Bottom Layer w10: v1(2989.94,3202.49) 3101.94,3202.49 cw(c3101.94,3169.49) v1(3134.94,3169.49) ; v1(3374.94,3869.49) 3476.22,3768.22 cw(c3418.94,3710.94) 3499.94,3710.94 v1(3499.94,3302.49)
OSC32_IN: C13.2 U1.3 Y2.2 | length 489.2
  Top Layer w10: U1.3 3338.13,4018.42 cw(c3348.49,4028.79) 3338.13,4039.15 3422.33,4123.35 cw(c3439.5,4106.17) 3456.68,4123.35 3479.81,4100.22 ccw(c3494.66,4115.07) 3509.51,4100.22 3546.36,4137.07 Y2.2 3557.48,4136.78 3579.21,4158.52 3658.98,4158.52 3660.37,4159.91 3675.57,4159.91 C13.2
OSC32_OUT: C14.2 U1.4 Y2.1 | length 459.8
  Top Layer w10: U1.4 3318.35,4010.36 cw(c3338.13,4030.13) 3318.35,4049.91 Y2.1 3495.94,4227.49 3495.94,4314.51 3497.33,4315.9 3497.33,4331.1 C14.2
OSC_IN: C11.2 U1.5 Y1.2 | length 477.6
  Top Layer w10: Y1.2 3230.24,4193.79 3195.94,4159.49 ccw(c3223.44,4131.99) 3195.94,4104.49 3270.94,4029.49 3271.38,4029.49 U1.5
  Top Layer w20: C11.2 Y1.2
OSC_OUT: C12.2 U1.6 Y1.1 | length 471.1
  Top Layer w10: Y1.1 3096.26,4059.06 3128.7,4091.49 cw(c3155.59,4064.6) 3182.48,4091.49 3185.47,4088.5 3250.04,4022.78 3250.25,4022.78 U1.6
  Top Layer w20: C12.2 Y1.1
PA0-WKUP: R8.2 U1.14 WKUP.2 | length 1976.9
  Top Layer w10: R8.2 cw(c2638.5,3135.05) 2640.94,3135.05 WKUP.2 2751.2,2978.09 cw(c2751.2,2935.34) 2793.94,2935.34 2793.94,2877.49 ccw(c2829.94,2877.49) 2829.94,2841.49 3043.94,2841.49 ccw(c3043.94,2874.49) 3076.94,2874.49 3076.94,3258.06 ; 3076.94,3258.09 cw(c3143.18,3258.06) 3096.34,3304.9 v1(3243.94,3452.49) ; U1.14 3269.4,3780.92 ccw(c3323.54,3835.06) 3323.51,3758.49 ; 3323.54,3758.49 v1(3428.94,3758.49)
  Bottom Layer w10: v1(3243.94,3452.49) 3407.74,3616.3 ccw(c3356.57,3667.47) 3428.94,3667.47 v1(3428.94,3758.49)
PA8: U1.41
PA11: U1.44
PA12: U1.45
PB0: U1.26
PB1: U1.27
PB2: U1.28
PB3: U1.55
PB4: U1.56
PB5: U1.57
PB6: U1.58
PB7: U1.59
PB8: U1.61
PB9: U1.62
PB10: U1.29
PB12: Ctrl.4 U1.33 | length 982.3
  Top Layer w10: U1.33 3712.32,3282.32 ccw(c3761.38,3331.38) 3761.38,3262 3900,3262 cw(c3900,3235.44) 3918.78,3254.22 4014,3159 cw(c3977.79,3122.79) 4029,3122.79 4029,3010 ccw(c4094.18,3010) 4048.07,2963.93 ; 4048.09,2963.91 4132,2880 Ctrl.4
PB13: Ctrl.3 U1.34 | length 895.2
  Top Layer w10: U1.34 3706.24,3316.24 ccw(c3767.18,3377.18) 3767.18,3291 3915,3291 cw(c3915,3254.79) 3940.61,3280.39 4040.15,3180.85 cw(c4004.3,3145) 4055,3145 4055,3090 ccw(c4108.11,3090) 4070.56,3052.44 Ctrl.3
PB14: Ctrl.2 U1.35 | length 826
  Top Layer w10: U1.35 3700.16,3350.16 ccw(c3768.15,3418.15) 3700.2,3350.12 ccw(c3768.15,3418.15) 3768.15,3322 3940,3322 cw(c3940,3288.2) 3963.89,3312.11 4065.15,3210.85 cw(c4029.3,3175) 4080,3175 4080,3152.92 ccw(c4132.92,3152.92) 4095.49,3115.51 4131,3080 Ctrl.2
PB15: Ctrl.1 U1.36 | length 741.8
  Top Layer w10: U1.36 3697.87,3380.29 ccw(c3768.58,3451) 3768.58,3351 3950,3351 cw(c3950,3297.89) 3987.55,3335.45 Ctrl.1
PC0: U1.8
PC4: U1.24
PC5: U1.25
PC8: U1.39
PC9: U1.40
PC13-TAMP: U1.2
SPI1_CLK: AD5541.2 U1.21 | length 1096.5
  Top Layer w10: U1.21 v1(3304.94,3703.93)
  Bottom Layer w10: AD5541.2 2441.87,3906.57 ccw(c2475.84,3940.54) 2475.83,3892.49 2481.37,3892.49 3151.94,3892.49 3304.94,3739.49 v1(3304.94,3703.93)
SPI1_CS: AD5541.3 U1.22 | length 1521.5
  Top Layer w10: AD5541.3 2407.94,4040.49 2439.94,4040.49 cw(c2439.94,4011.49) 2468.94,4011.49 2468.94,3614.49 ccw(c2506.94,3614.49) 2506.94,3576.49 v1(2879.94,3576.49) ; v1(3051.94,3576.49) 3072.44,3555.99 ccw(c3121.93,3605.49) 3121.93,3535.49 v1(3173.94,3535.49) ; U1.22 3290.82,3661.97 cw(c3318.64,3634.15) 3318.61,3673.49 ; 3318.64,3673.49 v1(3334.94,3673.49)
  Bottom Layer w10: v1(2879.94,3576.49) v1(3051.94,3576.49) ; v1(3173.94,3535.49) v1@3175.6,3535.49 ; v1@3175.63,3535.49 ccw(c3175.6,3587.01) 3212.03,3550.58 v1(3334.94,3673.49)
SPI1_SDA: AD5541.1 U1.23 | length 1428.6
  Top Layer w10: AD5541.1 2405.94,3581.61 ccw(c2448.05,3581.61) 2448.05,3539.49 2912.94,3539.49 v1(2915.94,3542.49) ; v1(3006.94,3544.49) 3032.97,3544.49 ; 3033,3544.49 cw(c3032.97,3503.52) 3061.94,3532.49 3073.94,3520.49 ccw(c3131.88,3578.44) 3131.79,3496.49 ccw(c3131.88,3578.44) 3131.88,3496.49 v1(3211.94,3496.49) ; U1.23 3299.45,3642.76 cw(c3311.3,3630.92) 3311.3,3647.67 3321.42,3647.67 cw(c3321.42,3613.53) 3345.56,3637.67 v1(3369.5,3613.73)
  Bottom Layer w10: v1(2915.94,3542.49) 3004.94,3542.49 v1(3006.94,3544.49) ; v1(3211.94,3496.49) 3234.46,3496.49 ccw(c3234.46,3539.46) 3234.53,3496.49 ccw(c3234.46,3539.46) 3264.85,3509.08 v1(3369.5,3613.73)
SPI3_CS: AD7175.4 U1.50 | length 579.2
  Top Layer w10: U1.50 U1.50@3713.24,3833.84 ; U1.50@3713.29,3833.84 4101.94,4222.49 AD7175.4
SPI3_MISO: AD7175.2 U1.52 | length 827.8
  Top Layer w10: U1.52 3971.94,4148.22 3971.94,4396.49 cw(c3997.94,4396.49) 3997.94,4422.49 AD7175.2
SPI3_MOSI: AD7175.1 U1.53 | length 936.5
  Top Layer w10: U1.53 3940.94,4145.06 3940.94,4493.49 cw(c3969.94,4493.49) 3969.94,4522.49 AD7175.1
SPI3_SCK: AD7175.3 U1.51 | length 712.9
  Top Layer w10: U1.51 4001.94,4150.38 4001.94,4284.49 cw(c4037.94,4284.49) 4037.94,4320.49 4103.94,4320.49 AD7175.3
SWCLK: SWD.2 U1.49 | length 1685.1
  Top Layer w10: U1.49 3820.71,3913.47 cw(c3861.81,3872.37) 3861.81,3930.49 v1(4044.94,3930.49)
  Bottom Layer w10: v1(4044.94,3930.49) 4240.94,3930.49 ccw(c4240.94,3968.49) 4278.94,3968.49 4278.94,4803.49 cw(c4303.94,4803.49) 4303.94,4828.49 4346.94,4828.49 ccw(c4346.94,4857.49) 4375.94,4857.49 SWD.2
SWDIO: SWD.3 U1.46 | length 2342
  Top Layer w10: U1.46 3734.35,3622.2 ccw(c3772.27,3660.12) 3772.26,3606.49 4239.94,3606.49 v1(4239.94,3607.49)
  Bottom Layer w10: v1(4239.94,3607.49) 4286.94,3607.49 ccw(c4286.94,3633.49) 4312.94,3633.49 4312.94,4480.49 ccw(c4312.94,4481.49) 4313.94,4481.49 4313.94,4504.49 cw(c4341.94,4504.49) 4341.94,4532.49 4390.94,4532.49 ccw(c4390.94,4567.49) 4425.94,4567.49 4425.94,4984.49 ccw(c4396.94,4984.49) 4396.94,5013.49 4300.94,5013.49 ccw(c4300.94,4988.49) 4275.94,4988.49 SWD.3
SYNC: AD7175.5 U1.54 | length 596.2
  Top Layer w10: U1.54 3685.64,3917.59 ccw(c3639.04,3964.2) 3704.94,3964.2 v1(3704.94,3991.49)
  Bottom Layer w10: v1(3704.94,3991.49) 3813.77,4100.32 cw(c3867.3,4046.78) 3867.24,4122.49 cw(c3867.3,4046.78) 3867.3,4122.49 AD7175.5
USART1_RX: U1.43 串口屏.2 | length 1325.6
  Top Layer w10: U1.43 3678.45,3594.58 ccw(c3707.63,3623.77) 3707.61,3582.49 ; 3707.63,3582.49 4207.51,3582.49 cw(c4207.51,3551) 4239,3551 4239,3413 ccw(c4272,3413) 4272,3380 4306,3380 cw(c4306,3346) 4340,3346 4340,3062 ccw(c4370,3062) 4370,3032 4449,3032 串口屏.2
USART1_TX: U1.42 串口屏.3 | length 1970.8
  Top Layer w10: U1.42 3668.06,3577.13 ccw(c3708.22,3617.29) 3708.22,3560.49 4160.51,3560.49 cw(c4160.51,3515) 4206,3515 4206,3372 ccw(c4233,3372) 4233,3345 4266,3345 cw(c4266,3306) 4305,3306 4305,2869 ccw(c4353,2869) 4353,2821 4484,2821 ccw(c4484,2881) 4544,2881 4544,3084.28 ccw(c4499.28,3084.28) 4499.28,3129 4454,3129 cw(c4454,3133) 串口屏.3
USART6_RX: D3.1 U1.38 | length 701.3
  Top Layer w10: U1.38 3513.04,3620.8 cw(c3533.44,3641.2) 3513.04,3661.59 3577.14,3725.7 cw(c3622.52,3680.32) 3622.52,3744.49 3878.08,3744.49 ccw(c3878.08,3762.35) 3895.94,3762.35 3895.94,3765.77 cw(c3912.58,3765.85) 3912.58,3782.49 D3.1
USART6_TX: R14.2 U1.37 | length 1153.6
  Top Layer w10: U1.37 3496.42,3609.58 cw(c3531.12,3644.28) 3496.42,3678.97 3561.56,3744.11 cw(c3605.94,3699.73) 3605.9,3762.49 ; 3605.94,3762.49 3839.94,3762.49 ccw(c3839.94,3787.49) 3864.94,3787.49 3864.94,3828.49 cw(c3885.94,3828.49) 3885.94,3849.49 4091.94,3849.49 cw(c4091.94,3824.49) 4116.94,3824.49 4116.94,3759.49 ccw(c4143.94,3759.49) 4143.94,3732.49 R14.2
VCC: C1.2 C2.2 C15.2 C16.2 C17.2 C18.2 U3.7 U4.7 U10.3 USB.2@3755.94,4957.49 VCC.1 串口屏.1 | length 5313.1
  Top Layer w20: U4.7 v1@3131.94,3442.49 ; v1(3089.94,3798.49) 3056.23,3798.49 3055.93,3798.19 3036.63,3798.19 U3.7 2985.94,3797.49 cw(c2985.94,3830.49) 2952.94,3830.49 2952.94,3883.37 ccw(c2858.5,3883.37) 2925.28,3950.16 2813.71,4061.72 cw(c2859.98,4107.99) 2813.71,4154.27 3088.14,4428.7 3088.21,4428.76 ccw(c2984.66,4532.31) 3131.1,4532.31 3131.1,4532.45 U10.3 C2.2 C1.2 VCC.1 3693.94,4572.49 ccw(c3693.94,4634.49) 3755.94,4634.49 USB.2@3755.94,4957.49
  Bottom Layer w20: C18.2 C17.2 ccw(c2961.94,3442.49) 2961.94,3441.49 3088.94,3441.49 ; C16.2 C15.2 2968.5,3852.49 3071.94,3852.49 cw(c3071.94,3834.49) 3089.94,3834.49 v1(3089.94,3798.49) 3089.94,3442.49 cw(c3088.94,3442.49) 3088.94,3441.49 ; 串口屏.1 4450,2726 cw(c4372.49,2726) 4372.49,2648.49 3234.48,2648.49 cw(c3234.48,2707.03) 3175.94,2707.03 3175.94,2707.16 3175.94,3395.4 ccw(c3129.85,3395.4) 3162.44,3427.99 3160.25,3430.18 ccw(c3132.94,3402.87) v1(3132.94,3441.49) 3089.94,3441.49 3088.94,3441.49
VCC_BOARD: D2.2 USB.1@3637.83,4957.49 | length 463.1
  Top Layer w20: D2.2 3593.94,5147.49 cw(c3593.94,5103.6) 3637.83,5103.6 3637.83,4958.6 USB.1@3637.83,4957.49
VCC_USB: USB.1@4504.09,4361.31 USB.3@3874.05,4957.49 | length 1175.5
  Top Layer w20: USB.3@3874.05,4957.49 3874.05,4839.38 ccw(c3925.94,4839.38) 3925.94,4787.49 4235.94,4787.49 cw(c4235.94,4747.49) 4275.94,4747.49 4275.94,4387.49 ccw(c4302.12,4387.49) 4302.12,4361.31 USB.1@4504.09,4361.31
VEE: C19.2 C20.2 C21.2 C22.2 D1.1 U3.4 U4.4 VEE.2 | length 3132.7
  Top Layer w20: v1(2530.94,4621.49) 2530.94,4673.49 cw(c2566.94,4673.49) 2566.94,4709.49 VEE.2 ccw(c2634.94,4710.49) 2635.94,4710.49 2635.94,4917.49 cw(c2687.36,4917.49) 2687.36,4968.91 D1.1 ; v1@2821.37,3288.49 U4.4 ; U3.4 2821.94,3697.49 v1(2821.94,3637.49)
  Bottom Layer w20: v1(2530.94,4621.49) 2530.94,4407.28 2530.94,4407.18 cw(c2486.26,4407.18) 2486.18,4362.49 2269.96,4362.49 ccw(c2269.88,4322.55) 2229.94,4322.55 2229.94,4322.41 2229.94,3691.35 2229.94,3691.21 ccw(c2283.66,3691.21) 2283.73,3637.49 v1(2821.94,3637.49) ; v1(2820.94,3288.49) ccw(c2820.94,3289.49) 2821.94,3289.49 2821.94,3324.35 ; C20.2 C19.2 2895.94,3694.49 2850.94,3694.49 ccw(c2850.94,3665.49) 2821.94,3665.49 v1(2821.94,3637.49) ; C22.2 C21.2 cw(c2899.94,3342.49) 2899.94,3341.49 2844.94,3341.49 ccw(c2844.94,3317.49) 2821.94,3324.35 ; 2821.94,3324.35 v1(2821.94,3637.49)
pads on no net: U1.1 U3.1 U3.5 U3.8 U4.1 U4.5 U4.8 U7.9 U7.10 U7.11 U7.12 U7.13 U7.14 U7.15 USB.4 USB.6 USB.MH1 USB.MH2
copper on no net:
  other v2: 2325.94,2727.49 4625.94,2727.49 2325.94,5077.49 4625.94,5077.49

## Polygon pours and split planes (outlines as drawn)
GND on Top Layer "GND_L01_P000" (solid, pour order 0): 2325.94,2597.49 cw(c2325.94,2727.49) 2195.94,2727.49 2195.94,5077.49 cw(c2325.94,5077.49) 2325.94,5207.49 4625.94,5207.49 cw(c4625.94,5077.49) 4755.94,5077.49 4755.94,2727.49 cw(c4625.94,2727.49) 4625.94,2597.49
GND on Bottom Layer "GND_L02_P001" (solid, pour order 1): 2325.94,2597.49 cw(c2325.94,2727.49) 2195.94,2727.49 2195.94,5077.49 cw(c2325.94,5077.49) 2325.94,5207.49 4625.94,5207.49 cw(c4625.94,5077.49) 4755.94,5077.49 4755.94,2727.49 cw(c4625.94,2727.49) 4625.94,2597.49

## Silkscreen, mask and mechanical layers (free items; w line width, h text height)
Top Overlay:
  text "3V3" at 4188.56,4824 h40 r90
  text "GND" at 4489.56,4810 h40 r90
  text "OP" at 3590,4802.89 h80
  text "SWDIO" at 4287.56,4768 h40 r90
  text "SWCLK" at 4388.56,4759 h40 r90
  text "8M" at 3334.69,4291.31 h40 r45
  text "12M" at 4257,3467 h40 r90
Bottom Overlay:
  drawing of 579 lines, arcs and shapes, not listed
  text "DIN" at 4062,4546 h30
  text "G" at 4258,4544.33 h30
  text "DOUT" at 4062,4439.33 h30
  text "G" at 4258,4439.33 h30
  text "SCLK" at 4062,4344.33 h30
  text "G" at 4258,4344.33 h30
  text "CS" at 4062,4253.33 h30
  text "G" at 4258,4253.33 h30
  text "SYNC" at 4062,4154.33 h30
  text "G" at 4258,4154.33 h30
  text "CS" at 2513,4031.33 h30
  text "G" at 2262,4030.33 h30
  text "CLK" at 2513,3936.33 h30
  text "G" at 2262,3932.33 h30
  text "SDA" at 2513,3834.33 h30
  text "G" at 2262,3832.33 h30
  text "GND" at 4398,3218.44 h40
  text "TX" at 4398,3117 h40
  text "RX" at 4394,3020 h40
  text "VCC" at 4393.96,2923.44 h40
  text "JLCJLCJLCJLC" at 3523.07,2608.44 h39.37
Bottom Solder:
  rectangle: 2200.32,3370.62 2415.32,3463.62
  rectangle: 2198,4794 2413,4887
Mechanical 1:
  lines w10: 2195.94,2727.49 ccw(c2325.94,2727.49) 2325.94,2597.49 4625.94,2597.49 ccw(c4625.94,2727.49) 4755.94,2727.49 4755.94,5077.49 ccw(c4625.94,5077.49) 4625.94,5207.49 2405.94,5207.49 2325.94,5207.49 ccw(c2325.94,5077.49) 2195.94,5077.49 2195.94,2727.49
